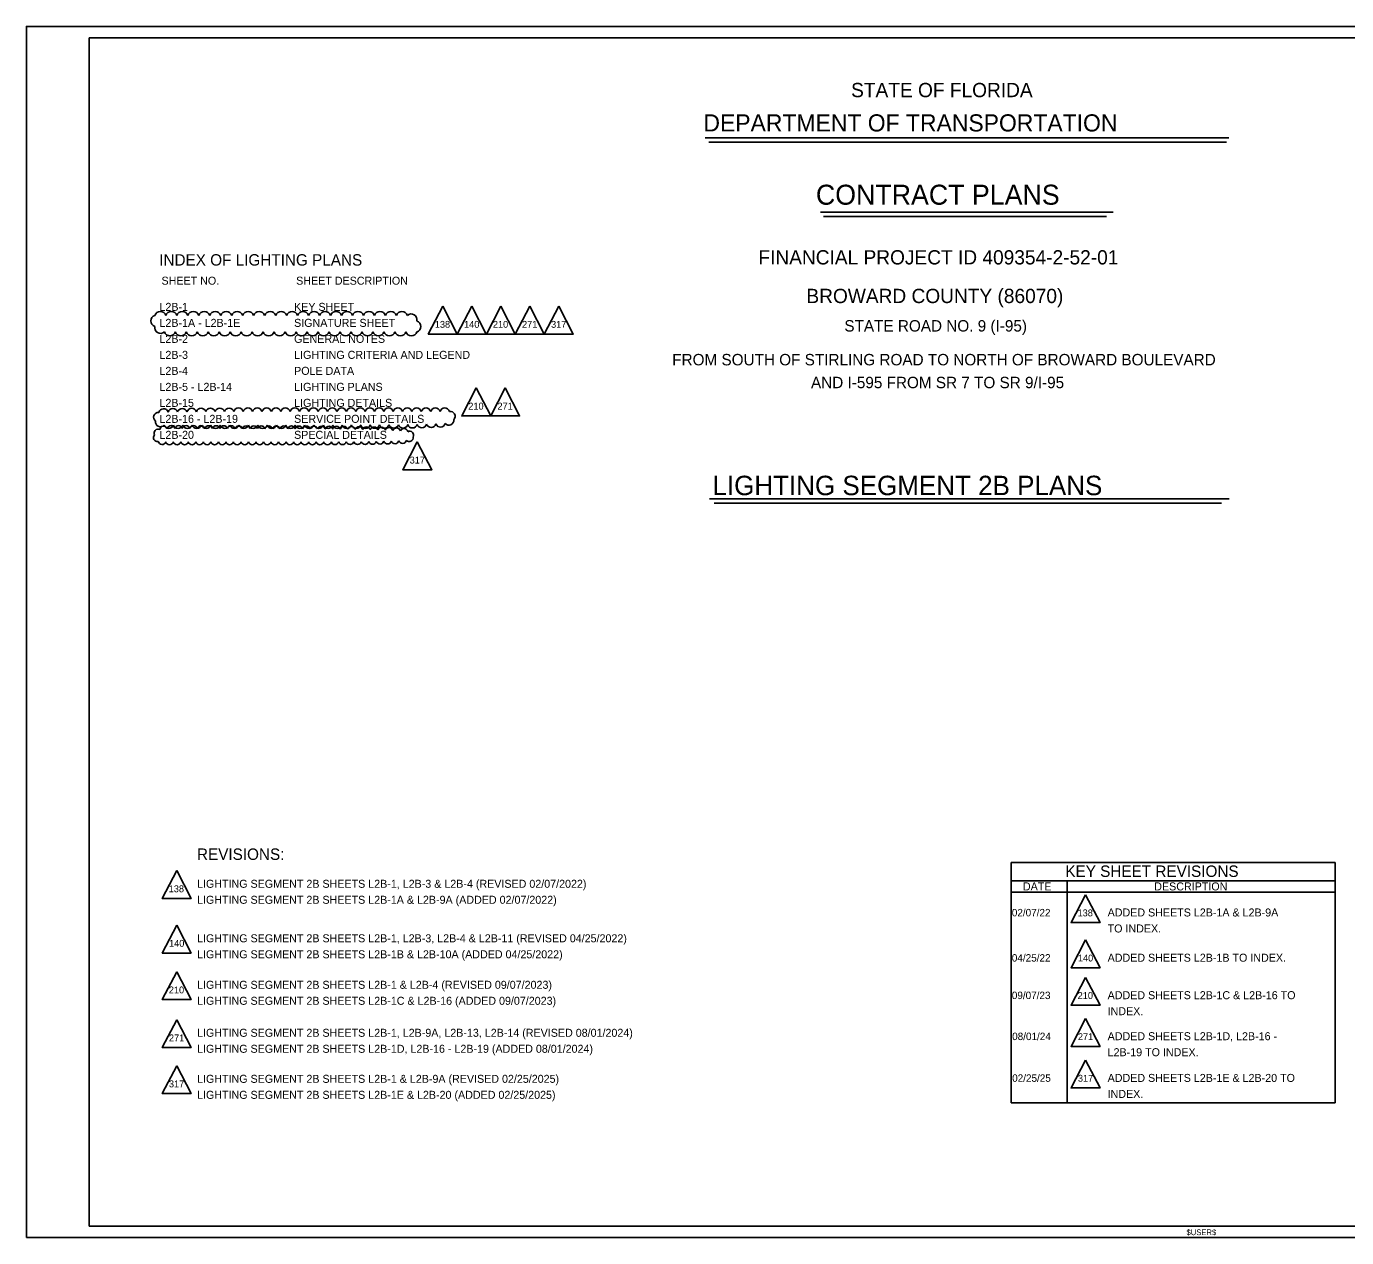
# Model space of a CAD drawing. Extents: x -820.2 to -798.1, y -2199.1 to -2188.5.
# Drawn here: x -820.23 to -808.68, y -2199.12 to -2188.52 of the extents above; entities that cross this region are included whole.
import ezdxf

# ---------------------------------------------------------------- set-up
doc = ezdxf.new("R2010")
doc.units = 0
for name, color, linetype in [('AdhocPoint_dp', 7, 'Continuous'), ('Cloud_dp', 7, 'Continuous'), ('PlotBorder_dp', 7, 'Continuous'), ('SheetBorder_dp', 7, 'Continuous'), ('SumBoxLines_dp', 7, 'Continuous'), ('TextLabel', 7, 'Continuous'), ('TextMinor', 7, 'Continuous'), ('TextNotes', 7, 'Continuous'), ('TextTitle', 7, 'Continuous')]:
    doc.layers.add(name, color=color, linetype=linetype)

msp = doc.modelspace()

# ---------------------------------------------------------------- linework, layer by layer
at = {"layer": 'AdhocPoint_dp'}
msp.add_line((-820.227, -2199.124), (-820.227, -2199.124), dxfattribs=at)
at = {"layer": 'Cloud_dp'}
for points in [[(-816.585, -2190.972), (-816.711, -2191.216), (-816.458, -2191.216)], [(-816.331, -2190.972), (-816.458, -2191.216), (-816.204, -2191.216)], [(-816.077, -2190.972), (-816.203, -2191.216), (-815.95, -2191.216)], [(-815.823, -2190.972), (-815.95, -2191.216), (-815.696, -2191.216)], [(-815.57, -2190.972), (-815.696, -2191.216), (-815.443, -2191.216)], [(-816.292, -2191.688), (-816.419, -2191.932), (-816.165, -2191.932)], [(-816.038, -2191.688), (-816.165, -2191.932), (-815.912, -2191.932)], [(-816.807, -2192.16), (-816.934, -2192.404), (-816.68, -2192.404)], [(-818.912, -2195.912), (-819.039, -2196.156), (-818.786, -2196.156)], [(-810.961, -2196.123), (-811.088, -2196.367), (-810.834, -2196.367)], [(-818.912, -2196.389), (-819.039, -2196.633), (-818.786, -2196.633)], [(-810.961, -2196.518), (-811.088, -2196.762), (-810.834, -2196.762)], [(-818.912, -2196.797), (-819.039, -2197.041), (-818.786, -2197.041)], [(-810.961, -2196.846), (-811.088, -2197.09), (-810.834, -2197.09)], [(-818.912, -2197.217), (-819.039, -2197.461), (-818.786, -2197.461)], [(-810.961, -2197.205), (-811.088, -2197.45), (-810.834, -2197.45)], [(-818.912, -2197.619), (-819.039, -2197.863), (-818.786, -2197.863)], [(-810.961, -2197.57), (-811.088, -2197.814), (-810.834, -2197.814)]]:
    msp.add_lwpolyline(points, close=True, dxfattribs=at)
for centre, radius, start, end in [((-819.088, -2191.101), 0.0504, 107.5, 252.5), ((-819.055, -2191.068), 0.0504, 17.5, 162.5), ((-818.959, -2191.068), 0.0504, 17.5, 162.5), ((-818.863, -2191.068), 0.0504, 17.5, 162.5), ((-818.767, -2191.068), 0.0504, 17.5, 162.5), ((-818.671, -2191.068), 0.0504, 17.5, 162.5), ((-818.575, -2191.068), 0.0504, 17.5, 162.5), ((-818.479, -2191.068), 0.0504, 17.5, 162.5), ((-818.383, -2191.068), 0.0504, 17.5, 162.5), ((-818.287, -2191.068), 0.0504, 17.5, 162.5), ((-818.191, -2191.068), 0.0504, 17.5, 162.5), ((-818.094, -2191.068), 0.0504, 17.5, 162.5), ((-817.998, -2191.068), 0.0504, 17.5, 162.5), ((-817.902, -2191.068), 0.0504, 17.5, 162.5), ((-817.806, -2191.068), 0.0504, 17.5, 162.5), ((-817.71, -2191.068), 0.0504, 17.5, 162.5), ((-817.614, -2191.068), 0.0504, 17.5, 162.5), ((-817.518, -2191.068), 0.0504, 17.5, 162.5), ((-817.422, -2191.068), 0.0504, 17.5, 162.5), ((-817.326, -2191.068), 0.0504, 17.5, 162.5), ((-817.23, -2191.068), 0.0504, 17.5, 162.5), ((-817.134, -2191.068), 0.0504, 17.5, 162.5), ((-817.038, -2191.068), 0.0504, 17.5, 162.5), ((-816.942, -2191.068), 0.0504, 17.5, 162.5), ((-816.86, -2191.09), 0.0503, 347.2695, 132.2695), ((-819.054, -2191.16), 0.0503, 167.2695, 312.2695), ((-816.826, -2191.15), 0.0504, 287.5, 72.5), ((-818.972, -2191.182), 0.0504, 197.5, 342.5), ((-818.876, -2191.182), 0.0504, 197.5, 342.5), ((-818.78, -2191.182), 0.0504, 197.5, 342.5), ((-818.684, -2191.182), 0.0504, 197.5, 342.5), ((-818.588, -2191.182), 0.0504, 197.5, 342.5), ((-818.492, -2191.182), 0.0504, 197.5, 342.5), ((-818.396, -2191.182), 0.0504, 197.5, 342.5), ((-818.3, -2191.182), 0.0504, 197.5, 342.5), ((-818.204, -2191.182), 0.0504, 197.5, 342.5), ((-818.108, -2191.182), 0.0504, 197.5, 342.5), ((-818.012, -2191.182), 0.0504, 197.5, 342.5), ((-817.915, -2191.182), 0.0504, 197.5, 342.5), ((-817.819, -2191.182), 0.0504, 197.5, 342.5), ((-817.723, -2191.182), 0.0504, 197.5, 342.5), ((-817.627, -2191.182), 0.0504, 197.5, 342.5), ((-817.531, -2191.182), 0.0504, 197.5, 342.5), ((-817.435, -2191.182), 0.0504, 197.5, 342.5), ((-817.339, -2191.182), 0.0504, 197.5, 342.5), ((-817.243, -2191.182), 0.0504, 197.5, 342.5), ((-817.147, -2191.182), 0.0504, 197.5, 342.5), ((-817.051, -2191.182), 0.0504, 197.5, 342.5), ((-816.955, -2191.182), 0.0504, 197.5, 342.5), ((-816.859, -2191.182), 0.0504, 197.5, 342.5), ((-819.027, -2191.913), 0.043, 19.3099, 164.3099), ((-818.945, -2191.911), 0.043, 18.5728, 163.5728), ((-818.863, -2191.91), 0.043, 18.2632, 163.2632), ((-818.781, -2191.909), 0.043, 18.0805, 163.0805), ((-818.699, -2191.908), 0.043, 17.9561, 162.9561), ((-818.617, -2191.907), 0.043, 17.8645, 162.8645), ((-818.535, -2191.907), 0.043, 17.7932, 162.7932), ((-818.453, -2191.907), 0.043, 17.7359, 162.7359), ((-818.371, -2191.906), 0.043, 17.6883, 162.6883), ((-818.289, -2191.906), 0.043, 17.6481, 162.6481), ((-818.207, -2191.906), 0.043, 17.6135, 162.6135), ((-818.125, -2191.906), 0.043, 17.5833, 162.5833), ((-818.043, -2191.906), 0.043, 17.5567, 162.5567), ((-817.961, -2191.906), 0.043, 17.533, 162.533), ((-817.879, -2191.906), 0.043, 17.5117, 162.5117), ((-817.797, -2191.906), 0.043, 17.5001, 162.5001), ((-817.715, -2191.906), 0.043, 17.5, 162.5), ((-817.633, -2191.906), 0.043, 17.5, 162.5), ((-817.551, -2191.906), 0.043, 17.5, 162.5), ((-817.469, -2191.906), 0.043, 17.5, 162.5), ((-817.387, -2191.906), 0.043, 17.5, 162.5), ((-817.305, -2191.906), 0.043, 17.5, 162.5), ((-817.223, -2191.906), 0.043, 17.5, 162.5), ((-817.141, -2191.906), 0.043, 17.5, 162.5), ((-817.059, -2191.906), 0.043, 17.5, 162.5), ((-816.977, -2191.906), 0.043, 17.5, 162.5), ((-816.895, -2191.906), 0.043, 17.5, 162.5), ((-816.813, -2191.906), 0.043, 17.5, 162.5), ((-816.731, -2191.906), 0.043, 17.5, 162.5), ((-816.649, -2191.906), 0.043, 17.5, 162.5), ((-816.567, -2191.906), 0.043, 17.5, 162.5), ((-819.071, -2191.944), 0.0429, 86.8577, 231.8577), ((-819.055, -2191.984), 0.043, 172.6222, 317.6222), ((-816.531, -2191.97), 0.043, 221.9316, 6.9316), ((-816.519, -2191.935), 0.043, 315.2071, 100.2071), ((-819.081, -2192.123), 0.0345, 136.6501, 281.6501), ((-819.075, -2192.083), 0.0345, 63.3075, 208.3075), ((-819.026, -2192.057), 0.0345, 26.8089, 171.8089), ((-818.982, -2192), 0.043, 197.5, 342.5), ((-818.962, -2192.052), 0.0345, 17.2934, 162.2934), ((-818.9, -2192), 0.043, 197.5, 342.5), ((-818.896, -2192.052), 0.0345, 17.2934, 162.2934), ((-818.83, -2192.052), 0.0345, 17.2934, 162.2934), ((-818.818, -2192), 0.043, 197.5, 342.5), ((-818.765, -2192.052), 0.0345, 17.2934, 162.2934), ((-818.736, -2192), 0.043, 197.5, 342.5), ((-818.699, -2192.053), 0.0345, 17.2934, 162.2934), ((-818.654, -2192), 0.043, 197.5, 342.5), ((-818.633, -2192.053), 0.0345, 17.2934, 162.2934), ((-818.572, -2192), 0.043, 197.5, 342.5), ((-818.567, -2192.053), 0.0345, 17.2934, 162.2934), ((-818.501, -2192.053), 0.0345, 17.2934, 162.2934), ((-818.49, -2192), 0.043, 197.5, 342.5), ((-818.436, -2192.053), 0.0345, 17.2934, 162.2934), ((-818.408, -2192), 0.043, 197.5, 342.5), ((-818.37, -2192.054), 0.0345, 17.2934, 162.2934), ((-818.326, -2192), 0.043, 197.5, 342.5), ((-818.304, -2192.054), 0.0345, 17.2934, 162.2934), ((-818.244, -2192), 0.043, 197.5, 342.5), ((-818.238, -2192.054), 0.0345, 17.2934, 162.2934), ((-818.172, -2192.054), 0.0345, 17.2934, 162.2934), ((-818.162, -2192), 0.043, 197.5, 342.5), ((-818.107, -2192.055), 0.0345, 17.2934, 162.2934), ((-818.08, -2192), 0.043, 197.5, 342.5), ((-818.041, -2192.055), 0.0345, 17.2934, 162.2934), ((-817.998, -2192), 0.043, 197.5, 342.5), ((-817.975, -2192.055), 0.0345, 17.2924, 162.2924), ((-817.916, -2192), 0.043, 197.5, 342.5), ((-817.909, -2192.055), 0.0345, 17.2594, 162.2594), ((-817.844, -2192.056), 0.0345, 17.2076, 162.2076), ((-817.834, -2192), 0.043, 197.5, 342.5), ((-817.778, -2192.056), 0.0345, 17.1502, 162.1502), ((-817.752, -2192), 0.043, 197.507, 342.507), ((-817.712, -2192.057), 0.0345, 17.0861, 162.0861), ((-817.67, -2192), 0.043, 197.5411, 342.5411), ((-817.646, -2192.057), 0.0345, 17.0141, 162.0141), ((-817.588, -2192), 0.043, 197.5814, 342.5814), ((-817.58, -2192.058), 0.0345, 16.9323, 161.9323), ((-817.506, -2192), 0.043, 197.6265, 342.6265), ((-817.515, -2192.058), 0.0345, 16.8382, 161.8382), ((-817.449, -2192.059), 0.0345, 16.7285, 161.7285), ((-817.424, -2191.999), 0.043, 197.6774, 342.6774), ((-817.383, -2192.06), 0.0345, 16.5982, 161.5982), ((-817.342, -2191.999), 0.043, 197.7355, 342.7355), ((-817.317, -2192.061), 0.0345, 16.44, 161.44), ((-817.26, -2191.999), 0.043, 197.8027, 342.8027), ((-817.252, -2192.063), 0.0345, 16.2423, 161.2423), ((-817.178, -2191.998), 0.043, 197.8816, 342.8816), ((-817.186, -2192.064), 0.0345, 15.9851, 160.9851), ((-817.12, -2192.066), 0.0345, 15.6312, 160.6312), ((-817.096, -2191.998), 0.043, 197.976, 342.976), ((-817.055, -2192.069), 0.0345, 15.0982, 160.0982), ((-817.014, -2191.997), 0.043, 198.0918, 343.0918), ((-816.989, -2192.072), 0.0345, 14.1512, 159.1512), ((-816.932, -2191.996), 0.043, 198.2386, 343.2386), ((-816.924, -2192.077), 0.0345, 11.4915, 156.4915), ((-816.85, -2191.995), 0.043, 198.4333, 343.4333), ((-816.874, -2192.101), 0.0345, 332.2398, 117.2398), ((-816.768, -2191.993), 0.043, 198.7095, 343.7095), ((-816.686, -2191.991), 0.043, 199.1475, 344.1475), ((-816.604, -2191.988), 0.043, 200.0205, 345.0205), ((-819.04, -2192.148), 0.0345, 193.7046, 338.7046), ((-818.975, -2192.15), 0.0345, 197.5, 342.5), ((-818.909, -2192.15), 0.0345, 197.5, 342.5), ((-818.843, -2192.15), 0.0345, 197.5, 342.5), ((-818.778, -2192.15), 0.0345, 197.5, 342.5), ((-818.712, -2192.15), 0.0345, 197.5, 342.5), ((-818.646, -2192.15), 0.0345, 197.5, 342.5), ((-818.58, -2192.15), 0.0345, 197.5, 342.5), ((-818.514, -2192.15), 0.0345, 197.5, 342.5), ((-818.449, -2192.15), 0.0345, 197.5, 342.5), ((-818.383, -2192.15), 0.0345, 197.5, 342.5), ((-818.317, -2192.15), 0.0345, 197.5, 342.5), ((-818.251, -2192.15), 0.0345, 197.5, 342.5), ((-818.186, -2192.15), 0.0345, 197.5, 342.5), ((-818.12, -2192.15), 0.0345, 197.5, 342.5), ((-818.054, -2192.15), 0.0345, 197.5, 342.5), ((-817.988, -2192.15), 0.0345, 197.5, 342.5), ((-817.922, -2192.15), 0.0345, 197.5027, 342.5027), ((-817.857, -2192.15), 0.0345, 197.5377, 342.5377), ((-817.791, -2192.15), 0.0345, 197.5857, 342.5857), ((-817.725, -2192.15), 0.0345, 197.6389, 342.6389), ((-817.659, -2192.15), 0.0345, 197.6983, 342.6983), ((-817.593, -2192.15), 0.0345, 197.7652, 342.7652), ((-817.528, -2192.149), 0.0345, 197.8413, 342.8413), ((-817.462, -2192.149), 0.0345, 197.9291, 342.9291), ((-817.396, -2192.148), 0.0345, 198.0316, 343.0316), ((-817.33, -2192.148), 0.0345, 198.1538, 343.1538), ((-817.265, -2192.147), 0.0345, 198.3027, 343.3027), ((-817.199, -2192.146), 0.0345, 198.4898, 343.4898), ((-817.133, -2192.144), 0.0345, 198.7348, 343.7348), ((-817.067, -2192.143), 0.0345, 199.076, 344.076), ((-817.002, -2192.141), 0.0345, 199.5995, 344.5995), ((-816.936, -2192.138), 0.0345, 200.5676, 345.5676), ((-816.878, -2192.122), 0.0345, 224.0303, 9.0303)]:
    msp.add_arc(centre, radius, start, end, dxfattribs=at)
at = {"layer": 'PlotBorder_dp'}
msp.add_lwpolyline([(-820.227, -2199.124), (-803.727, -2199.124), (-803.727, -2188.524), (-820.227, -2188.524)], close=True, dxfattribs=at)
at = {"layer": 'SheetBorder_dp'}
for p, q in [((-819.677, -2188.624), (-819.677, -2199.024)), ((-819.677, -2188.624), (-804.277, -2188.624)), ((-819.677, -2199.024), (-804.277, -2199.024))]:
    msp.add_line(p, q, dxfattribs=at)
at = {"layer": 'SumBoxLines_dp'}
for p, q in [((-811.612, -2195.84), (-811.612, -2197.943)), ((-811.612, -2195.84), (-808.777, -2195.84)), ((-808.777, -2195.84), (-808.777, -2197.943)), ((-811.612, -2196), (-808.777, -2196)), ((-811.122, -2196), (-811.122, -2197.943)), ((-811.612, -2196.1), (-808.777, -2196.1)), ((-811.612, -2197.943), (-808.777, -2197.943))]:
    msp.add_line(p, q, dxfattribs=at)
at = {"layer": 'TextTitle'}
for p, q in [((-814.289, -2189.5), (-809.707, -2189.5)), ((-814.257, -2189.538), (-809.729, -2189.538)), ((-813.281, -2190.15), (-810.719, -2190.15)), ((-813.253, -2190.188), (-810.777, -2190.188)), ((-814.252, -2192.659), (-809.704, -2192.659)), ((-814.209, -2192.697), (-809.772, -2192.697))]:
    msp.add_line(p, q, dxfattribs=at)

# ---------------------------------------------------------------- texts
at = {"layer": 'Cloud_dp'}
for s, p in [('138', (-816.654, -2191.161)), ('140', (-816.398, -2191.161)), ('210', (-816.146, -2191.161)), ('271', (-815.891, -2191.161)), ('317', (-815.637, -2191.161)), ('210', (-816.361, -2191.877)), ('271', (-816.106, -2191.877)), ('317', (-816.874, -2192.349)), ('138', (-818.982, -2196.101)), ('138', (-811.031, -2196.312)), ('140', (-818.979, -2196.578)), ('140', (-811.028, -2196.707)), ('210', (-818.981, -2196.986)), ('210', (-811.03, -2197.035)), ('271', (-818.98, -2197.406)), ('271', (-811.028, -2197.395)), ('317', (-818.98, -2197.808)), ('317', (-811.028, -2197.759))]:
    msp.add_text(s, height=0.06, rotation=0, dxfattribs=at).set_placement(p)
at = {"layer": 'TextLabel'}
for s, height, p in [('FINANCIAL PROJECT ID 409354-2-52-01', 0.125, (-813.823, -2190.607)), ('INDEX OF LIGHTING PLANS', 0.1, (-819.065, -2190.617)), ('BROWARD COUNTY (86070)', 0.125, (-813.403, -2190.945)), ('L2B-1', 0.07, (-819.063, -2191.013)), ('KEY SHEET', 0.07, (-817.885, -2191.013)), ('L2B-1A - L2B-1E', 0.07, (-819.063, -2191.153)), ('SIGNATURE SHEET', 0.07, (-817.885, -2191.153)), ('STATE ROAD NO. 9 (I-95)', 0.1, (-813.071, -2191.194)), ('L2B-2', 0.07, (-819.063, -2191.293)), ('GENERAL NOTES', 0.07, (-817.885, -2191.293)), ('L2B-3', 0.07, (-819.063, -2191.433)), ('LIGHTING CRITERIA AND LEGEND', 0.07, (-817.885, -2191.433)), ('FROM SOUTH OF STIRLING ROAD TO NORTH OF BROWARD BOULEVARD', 0.1, (-814.577, -2191.49)), ('L2B-4', 0.07, (-819.063, -2191.573)), ('POLE DATA', 0.07, (-817.885, -2191.573)), ('L2B-5 - L2B-14', 0.07, (-819.063, -2191.713)), ('LIGHTING PLANS', 0.07, (-817.885, -2191.713)), ('AND I-595 FROM SR 7 TO SR 9/I-95', 0.1, (-813.363, -2191.69)), ('L2B-15', 0.07, (-819.063, -2191.853)), ('LIGHTING DETAILS', 0.07, (-817.885, -2191.853)), ('L2B-16 - L2B-19', 0.07, (-819.063, -2191.993)), ('SERVICE POINT DETAILS', 0.07, (-817.885, -2191.993)), ('L2B-20', 0.07, (-819.063, -2192.133)), ('SPECIAL DETAILS', 0.07, (-817.885, -2192.133)), ('REVISIONS:', 0.1, (-818.735, -2195.818)), ('KEY SHEET REVISIONS', 0.1, (-811.138, -2195.967))]:
    msp.add_text(s, height=height, dxfattribs=at).set_placement(p)
at = {"layer": 'TextMinor'}
for s, height, p in [('02/07/22', 0.065, (-811.606, -2196.312)), ('ADDED SHEETS L2B-1A & L2B-9A ', 0.07, (-810.768, -2196.313)), ('TO INDEX.', 0.07, (-810.768, -2196.453)), ('04/25/22', 0.065, (-811.606, -2196.708)), ('ADDED SHEETS L2B-1B TO INDEX.', 0.07, (-810.768, -2196.709)), ('09/07/23', 0.065, (-811.606, -2197.036)), ('ADDED SHEETS L2B-1C & L2B-16 TO ', 0.07, (-810.768, -2197.037)), ('INDEX.', 0.07, (-810.768, -2197.177)), ('08/01/24', 0.065, (-811.603, -2197.395)), ('ADDED SHEETS L2B-1D, L2B-16 - ', 0.07, (-810.768, -2197.396)), ('L2B-19 TO INDEX.', 0.07, (-810.768, -2197.536)), ('02/25/25', 0.065, (-811.603, -2197.76)), ('ADDED SHEETS L2B-1E & L2B-20 TO ', 0.07, (-810.768, -2197.761)), ('INDEX.', 0.07, (-810.768, -2197.901)), ('$USER$', 0.05, (-810.078, -2199.102))]:
    msp.add_text(s, height=height, dxfattribs=at).set_placement(p)
at = {"layer": 'TextNotes'}
for s, height, p in [('SHEET NO.', 0.07, (-819.045, -2190.784)), ('SHEET DESCRIPTION', 0.07, (-817.867, -2190.784)), ('LIGHTING SEGMENT 2B SHEETS L2B-1, L2B-3 & L2B-4 (REVISED 02/07/2022)', 0.06998, (-818.734, -2196.062)), ('DATE', 0.07, (-811.509, -2196.085)), ('DESCRIPTION', 0.07, (-810.36, -2196.085)), ('LIGHTING SEGMENT 2B SHEETS L2B-1A & L2B-9A (ADDED 02/07/2022)', 0.06998, (-818.734, -2196.202)), ('LIGHTING SEGMENT 2B SHEETS L2B-1, L2B-3, L2B-4 & L2B-11 (REVISED 04/25/2022)', 0.06998, (-818.734, -2196.539)), ('LIGHTING SEGMENT 2B SHEETS L2B-1B & L2B-10A (ADDED 04/25/2022)', 0.06998, (-818.734, -2196.679)), ('LIGHTING SEGMENT 2B SHEETS L2B-1 & L2B-4 (REVISED 09/07/2023)', 0.06998, (-818.734, -2196.946)), ('LIGHTING SEGMENT 2B SHEETS L2B-1C & L2B-16 (ADDED 09/07/2023)', 0.06998, (-818.734, -2197.086)), ('LIGHTING SEGMENT 2B SHEETS L2B-1, L2B-9A, L2B-13, L2B-14 (REVISED 08/01/2024)', 0.06998, (-818.734, -2197.366)), ('LIGHTING SEGMENT 2B SHEETS L2B-1D, L2B-16 - L2B-19 (ADDED 08/01/2024)', 0.06998, (-818.734, -2197.506)), ('LIGHTING SEGMENT 2B SHEETS L2B-1 & L2B-9A (REVISED 02/25/2025)', 0.06998, (-818.734, -2197.769)), ('LIGHTING SEGMENT 2B SHEETS L2B-1E & L2B-20 (ADDED 02/25/2025)', 0.06998, (-818.734, -2197.909))]:
    msp.add_text(s, height=height, dxfattribs=at).set_placement(p)
at = {"layer": 'TextTitle'}
for s, height, p in [('STATE OF FLORIDA', 0.125, (-813.012, -2189.143)), ('DEPARTMENT OF TRANSPORTATION', 0.15, (-814.304, -2189.443)), ('CONTRACT PLANS', 0.175, (-813.32, -2190.084)), ('LIGHTING SEGMENT 2B PLANS', 0.17, (-814.225, -2192.626))]:
    msp.add_text(s, height=height, dxfattribs=at).set_placement(p)

doc.saveas('drawing.dxf')
